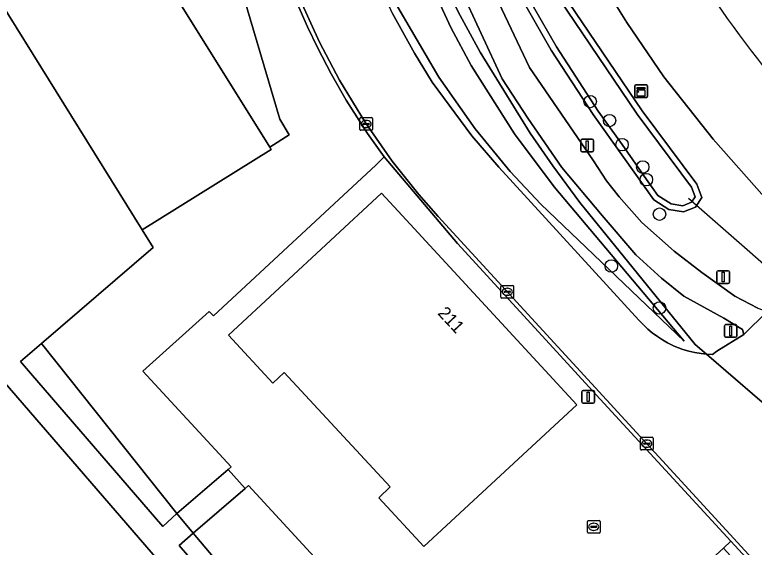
# Model space of a CAD drawing. Extents: x 156061 to 157804, y 383437 to 385640.
# Drawn here: x 157607.2 to 157665.5, y 383655.1 to 383697 of the extents above; entities that cross this region are included whole.
import ezdxf

# ---------------------------------------------------------------- set-up
doc = ezdxf.new("R2010")
doc.units = 0
for name, color, linetype in [('IMGEO_Berm_groen', 7, 'Continuous'), ('IMGEO_Boom', 7, 'Continuous'), ('IMGEO_Duiker', 7, 'Continuous'), ('IMGEO_Erf', 7, 'Continuous'), ('IMGEO_Fietspad_gesloten', 7, 'Continuous'), ('IMGEO_Grasland_overig', 7, 'Continuous'), ('IMGEO_Groenvoorziening', 7, 'Continuous'), ('IMGEO_Hek', 7, 'Continuous'), ('IMGEO_Kast', 7, 'Continuous'), ('IMGEO_Kolk', 7, 'Continuous'), ('IMGEO_Lichtmast', 7, 'Continuous'), ('IMGEO_Meer_plas_ven_vijver', 7, 'Continuous'), ('IMGEO_Oever', 7, 'Continuous'), ('IMGEO_Pand', 7, 'Continuous'), ('IMGEO_Pand_nummerreeks', 7, 'Continuous'), ('IMGEO_Rijbaan_lokaal_gesloten', 7, 'Continuous'), ('IMGEO_Rijbaan_lokaal_open', 7, 'Continuous'), ('IMGEO_Verkeersbordpaal', 7, 'Continuous'), ('IMGEO_Voetpad_gesloten', 7, 'Continuous'), ('IMGEO_Waterloop', 7, 'Continuous')]:
    doc.layers.add(name, color=color, linetype=linetype)

msp = doc.modelspace()

# ---------------------------------------------------------------- linework, layer by layer
at = {"layer": 'IMGEO_Berm_groen'}
msp.add_lwpolyline([(157656.632, 383689.474), (157660.937, 383683.676), (157661.345, 383682.627), (157660.835, 383681.881), (157659.893, 383681.496), (157658.745, 383681.699), (157657.555, 383682.443), (157652.785, 383689.179), (157649.474, 383694.263), (157647.042, 383698.509), (157644.296, 383704.009), (157630.634, 383737.612), (157621.052, 383760.833), (157597.456, 383819.12), (157599.565, 383819.919), (157622.01, 383766.684), (157628.75, 383750), (157632.796, 383738.492), (157645.394, 383707.875), (157649.283, 383700.352)], close=True, dxfattribs=at)
for points in [[(157619.12, 383759.995), (157619.272, 383759.605), (157619.425, 383759.216), (157621.18, 383754.837), (157623.144, 383750), (157627.643, 383739.156), (157638.747, 383712.974), (157643.168, 383702.614), (157647.755, 383692.88), (157652.793, 383685.539), (157653.818, 383683.942), (157654.817, 383682.694), (157656.624, 383680.676), (157659.165, 383678.4), (157661.336, 383676.722), (157663.95, 383674.865), (157665.764, 383673.914), (157666.48, 383673.644), (157666.827, 383674.423), (157667.128, 383675.025), (157667.375, 383675.651), (157667.541, 383676.205)], [(157666.28, 383682.654), (157662.238, 383687.235), (157658.348, 383692.157), (157655.418, 383696.421), (157653.189, 383700.032), (157646.921, 383712.29), (157641.684, 383723.88), (157630.958, 383750)]]:
    msp.add_lwpolyline(points, dxfattribs=at)
at = {"layer": 'IMGEO_Boom'}
for centre in [(157652.54, 383690.2), (157654.069, 383688.702), (157655.052, 383686.803), (157656.682, 383685.039), (157656.967, 383684.044), (157658.002, 383681.323), (157654.208, 383677.236), (157658.006, 383673.93)]:
    msp.add_circle(centre, 0.489, dxfattribs=at)
at = {"layer": 'IMGEO_Duiker'}
msp.add_lwpolyline([(157680.128, 383665.155), (157679.878, 383665.374), (157673.509, 383670.965), (157667.541, 383676.205), (157665.124, 383678.326), (157660.298, 383682.563)], dxfattribs=at)
at = {"layer": 'IMGEO_Erf'}
for points in [[(157634.437, 383638.653), (157620.132, 383655.218), (157621.256, 383656.181), (157619.968, 383657.726), (157618.847, 383656.716), (157608.419, 383668.784), (157607.636, 383669.704), (157609.282, 383671.12), (157618.102, 383678.709), (157617.211, 383680.099), (157604.846, 383699.969), (157614.994, 383706.315), (157627.287, 383686.608), (157628.823, 383687.576), (157628.075, 383688.812), (157620.719, 383713.705), (157622.915, 383714.315), (157620.859, 383719.471), (157613.417, 383738.127), (157582.968, 383711.822)], [(157546.586, 383690.669), (157569.551, 383710.587), (157574.434, 383704.864), (157580.09, 383698.235), (157589.181, 383706.103), (157593.316, 383701.326), (157584.203, 383693.494), (157589.969, 383686.975), (157592.085, 383684.583), (157592.743, 383683.81), (157631.604, 383638.864)]]:
    msp.add_lwpolyline(points, dxfattribs=at)
for points in [[(157663.038, 383655.013), (157663.63, 383655.554), (157652.735, 383667.414), (157649.055, 383671.421), (157642.073, 383679.016), (157636.298, 383685.833), (157635.64, 383685.18), (157622.846, 383673.301), (157622.498, 383673.653), (157617.28, 383668.944), (157624.23, 383661.417), (157624.003, 383661.197), (157625.333, 383659.711), (157625.613, 383659.933), (157645.162, 383638.719), (157646.075, 383639.53), (157646.224, 383639.429), (157647.765, 383640.669), (157647.565, 383640.888)], [(157639.423, 383655.14), (157635.882, 383658.959), (157636.783, 383659.847), (157628.424, 383668.849), (157627.528, 383668.013), (157624.022, 383671.797), (157636.09, 383682.98), (157637.392, 383681.569), (157651.485, 383666.295)]]:
    msp.add_lwpolyline(points, close=True, dxfattribs=at)
at = {"layer": 'IMGEO_Fietspad_gesloten'}
for points in [[(157620.857, 383750), (157625.641, 383738.364), (157636.444, 383712.133), (157640.636, 383702.745), (157645.615, 383692.003), (157647.612, 383688.893), (157650.31, 383684.991), (157653.473, 383681.227), (157656.137, 383678.12), (157658.153, 383676.273), (157659.933, 383674.868), (157663.084, 383673.125), (157664.534, 383672.23), (157664.66, 383671.828), (157666.48, 383673.644)], [(157665.764, 383673.914), (157663.95, 383674.865), (157661.336, 383676.722), (157659.165, 383678.4), (157656.624, 383680.676), (157654.817, 383682.694), (157653.818, 383683.942), (157652.793, 383685.539), (157647.755, 383692.88), (157643.168, 383702.614), (157638.747, 383712.974), (157627.643, 383739.156)]]:
    msp.add_lwpolyline(points, dxfattribs=at)
at = {"layer": 'IMGEO_Grasland_overig'}
for points in [[(157617.211, 383680.099), (157618.102, 383678.709), (157609.282, 383671.12), (157619.968, 383657.726), (157624.003, 383661.197), (157624.23, 383661.417), (157617.28, 383668.944), (157622.498, 383673.653), (157622.846, 383673.301), (157635.64, 383685.18), (157636.298, 383685.833), (157634.986, 383687.693), (157633.31, 383690.317), (157632.13, 383692.372), (157631.063, 383694.413), (157630.259, 383696.094), (157629.402, 383698.056), (157622.915, 383714.315), (157620.719, 383713.705), (157628.075, 383688.812), (157628.823, 383687.576), (157627.287, 383686.608), (157627.398, 383686.431)], [(157609.282, 383671.12), (157607.636, 383669.704), (157608.419, 383668.784), (157618.847, 383656.716), (157619.968, 383657.726)]]:
    msp.add_lwpolyline(points, close=True, dxfattribs=at)
at = {"layer": 'IMGEO_Groenvoorziening'}
for points in [[(157649.7, 383683.481), (157646.562, 383687.66), (157643.168, 383693.05), (157641.568, 383696.029), (157639.454, 383700.6), (157637.598, 383705.528), (157619.357, 383750), (157608.011, 383777.219), (157590.971, 383816.65), (157589.147, 383814.382), (157615.621, 383750), (157634.608, 383703.827), (157637.39, 383697.645), (157640.601, 383692.115), (157643.471, 383688.052), (157646.245, 383684.678), (157648.645, 383682.101), (157659.948, 383671.324)], [(157659.948, 383671.324), (157648.645, 383682.101), (157646.245, 383684.678), (157643.471, 383688.052), (157640.601, 383692.115), (157637.39, 383697.645), (157634.608, 383703.827), (157615.621, 383750), (157589.147, 383814.382), (157590.971, 383816.65), (157608.011, 383777.219), (157619.357, 383750), (157637.598, 383705.528), (157639.454, 383700.6), (157641.568, 383696.029), (157643.168, 383693.05), (157646.562, 383687.66), (157649.7, 383683.481)], [(157617.318, 383607.508), (157617.189, 383609.565), (157623.911, 383616.901), (157639.22, 383630.176), (157647.699, 383637.528), (157646.224, 383639.429), (157646.075, 383639.53), (157645.162, 383638.719), (157625.613, 383659.933), (157625.333, 383659.711), (157621.256, 383656.181), (157636.145, 383638.565), (157633.728, 383636.44), (157614.798, 383619.797), (157598.3, 383603.675), (157604.166, 383597.049), (157613.461, 383586.57), (157620.486, 383578.692), (157622.825, 383576.06), (157630.214, 383582.846), (157612.047, 383603.052)], [(157596.405, 383605.765), (157598.042, 383603.967), (157598.3, 383603.675), (157614.798, 383619.797), (157633.728, 383636.44), (157636.145, 383638.565), (157621.256, 383656.181), (157620.132, 383655.218), (157634.437, 383638.653), (157632.931, 383637.35)]]:
    msp.add_lwpolyline(points, close=True, dxfattribs=at)
for points in [[(157640.011, 383701.544), (157642.293, 383696.97), (157643.878, 383694.087), (157647.814, 383687.72), (157649.591, 383685.145), (157651.737, 383682.237), (157660.817, 383671.051), (157661.711, 383670.281), (157662.188, 383670.253), (157662.52, 383670.523), (157664.66, 383671.828), (157664.534, 383672.23), (157663.084, 383673.125), (157659.933, 383674.868), (157658.153, 383676.273), (157656.137, 383678.12), (157653.473, 383681.227), (157650.31, 383684.991), (157647.612, 383688.893), (157645.615, 383692.003), (157640.636, 383702.745)], [(157636.963, 383697.145), (157638.679, 383694.001), (157640.091, 383691.739), (157643.2, 383687.496), (157645.33, 383685.028), (157656.375, 383672.981), (157656.769, 383672.566), (157657.096, 383672.261), (157657.431, 383671.982), (157657.842, 383671.678), (157658.251, 383671.413), (157658.639, 383671.193), (157659.172, 383670.934), (157659.856, 383670.669), (157660.315, 383670.53), (157660.784, 383670.418), (157661.278, 383670.331), (157661.711, 383670.281), (157660.817, 383671.051), (157651.737, 383682.237), (157649.591, 383685.145), (157647.814, 383687.72), (157643.878, 383694.087), (157642.293, 383696.97), (157640.011, 383701.544)], [(157669.795, 383648.842), (157663.63, 383655.554), (157663.038, 383655.013), (157670.77, 383646.55)]]:
    msp.add_lwpolyline(points, dxfattribs=at)
msp.add_arc((157737.195, 383749.157), 90.556, 213.33611, 229.48121, dxfattribs=at)
at = {"layer": 'IMGEO_Hek'}
for points in [[(157661.711, 383670.281), (157660.817, 383671.051), (157651.737, 383682.237), (157649.591, 383685.145), (157647.814, 383687.72), (157643.878, 383694.087), (157642.293, 383696.97), (157640.011, 383701.544), (157637.106, 383708.345), (157620.09, 383750)], [(157667.614, 383665.197), (157661.711, 383670.281)]]:
    msp.add_lwpolyline(points, dxfattribs=at)
at = {"layer": 'IMGEO_Kast'}
for p, q in [((157656.052, 383690.585), (157656.052, 383691.426)), ((157656.052, 383691.426), (157656.052, 383690.585)), ((157656.127, 383691.51), (157656.968, 383691.51)), ((157656.968, 383691.51), (157656.127, 383691.51)), ((157657.052, 383691.435), (157657.052, 383690.594)), ((157657.052, 383690.594), (157657.052, 383691.435)), ((157656.977, 383690.51), (157656.136, 383690.51)), ((157656.136, 383690.51), (157656.977, 383690.51))]:
    msp.add_line(p, q, dxfattribs=at)
for points in [[(157656.247, 383691.3), (157656.847, 383691.3), (157656.847, 383691.215), (157656.247, 383691.215), (157656.247, 383691.3)], [(157656.247, 383691.125), (157656.847, 383691.125), (157656.847, 383690.636), (157656.247, 383690.636), (157656.247, 383691.125)]]:
    msp.add_lwpolyline(points, dxfattribs=at)
msp.add_circle((157656.331, 383690.974), 0.0377, dxfattribs=at)
for centre, start, end in [((157656.13, 383691.432), 92.4484, 184.28452), ((157656.13, 383691.432), 92.4484, 184.28452), ((157656.974, 383691.432), 2.4484, 94.28452), ((157656.974, 383691.432), 2.4484, 94.28452), ((157656.13, 383690.588), 182.4484, 274.28452), ((157656.13, 383690.588), 182.4484, 274.28452), ((157656.974, 383690.588), 272.4484, 4.28452), ((157656.974, 383690.588), 272.4484, 4.28452)]:
    msp.add_arc(centre, 0.0779, start, end, dxfattribs=at)
at = {"layer": 'IMGEO_Kolk'}
for p, q in [((157634.382, 383688.008), (157634.382, 383688.86)), ((157634.457, 383688.934), (157635.309, 383688.934)), ((157635.383, 383688.86), (157635.383, 383688.008)), ((157634.641, 383688.428), (157634.641, 383688.44)), ((157635.079, 383688.391), (157634.681, 383688.391)), ((157634.684, 383688.477), (157635.082, 383688.477)), ((157634.87, 383688.714), (157634.895, 383688.714)), ((157635.125, 383688.44), (157635.125, 383688.428)), ((157635.309, 383687.934), (157634.457, 383687.934)), ((157634.893, 383688.154), (157634.868, 383688.154)), ((157645.507, 383674.782), (157645.507, 383675.634)), ((157645.582, 383675.708), (157646.434, 383675.708)), ((157645.995, 383675.488), (157646.02, 383675.488)), ((157646.508, 383675.634), (157646.508, 383674.782)), ((157645.766, 383675.202), (157645.766, 383675.214)), ((157646.204, 383675.165), (157645.806, 383675.165)), ((157645.809, 383675.251), (157646.207, 383675.251)), ((157646.018, 383674.928), (157645.993, 383674.928)), ((157646.25, 383675.214), (157646.25, 383675.202)), ((157646.434, 383674.708), (157645.582, 383674.708)), ((157656.574, 383663.738), (157657.426, 383663.738)), ((157656.499, 383662.812), (157656.499, 383663.664)), ((157656.758, 383663.232), (157656.758, 383663.244)), ((157657.196, 383663.195), (157656.798, 383663.195)), ((157656.801, 383663.281), (157657.199, 383663.281)), ((157656.987, 383663.518), (157657.012, 383663.518)), ((157657.242, 383663.244), (157657.242, 383663.232)), ((157657.5, 383663.664), (157657.5, 383662.812)), ((157657.426, 383662.738), (157656.574, 383662.738)), ((157657.01, 383662.958), (157656.985, 383662.958)), ((157652.319, 383656.255), (157652.319, 383657.107)), ((157652.394, 383657.181), (157653.246, 383657.181)), ((157652.621, 383656.724), (157653.019, 383656.724)), ((157652.807, 383656.961), (157652.832, 383656.961)), ((157653.32, 383657.107), (157653.32, 383656.255)), ((157653.246, 383656.181), (157652.394, 383656.181)), ((157652.578, 383656.675), (157652.578, 383656.687)), ((157653.016, 383656.638), (157652.618, 383656.638)), ((157652.83, 383656.401), (157652.805, 383656.401)), ((157653.062, 383656.687), (157653.062, 383656.675))]:
    msp.add_line(p, q, dxfattribs=at)
for points in [[(157634.382, 383688.008), (157634.382, 383688.86)], [(157634.457, 383688.934), (157635.309, 383688.934)], [(157635.383, 383688.86), (157635.383, 383688.008)], [(157635.309, 383687.934), (157634.457, 383687.934)], [(157645.507, 383674.782), (157645.507, 383675.634)], [(157645.582, 383675.708), (157646.434, 383675.708)], [(157646.508, 383675.634), (157646.508, 383674.782)], [(157646.434, 383674.708), (157645.582, 383674.708)], [(157656.574, 383663.738), (157657.426, 383663.738)], [(157656.499, 383662.812), (157656.499, 383663.664)], [(157657.5, 383663.664), (157657.5, 383662.812)], [(157657.426, 383662.738), (157656.574, 383662.738)], [(157652.319, 383656.255), (157652.319, 383657.107)], [(157652.394, 383657.181), (157653.246, 383657.181)], [(157653.32, 383657.107), (157653.32, 383656.255)], [(157653.246, 383656.181), (157652.394, 383656.181)]]:
    msp.add_lwpolyline(points, dxfattribs=at)
for centre, radius, start, end in [((157634.459, 383688.858), 0.0765, 91.55205, 178.44795), ((157634.459, 383688.858), 0.0765, 91.55205, 178.44795), ((157635.307, 383688.858), 0.0765, 1.55205, 88.44795), ((157635.307, 383688.858), 0.0765, 1.55205, 88.44795), ((157634.681, 383688.437), 0.0403, 85.87752, 175.75265), ((157634.678, 383688.427), 0.0366, 178.93798, 274.71019), ((157635.082, 383688.434), 0.043, 264.86636, 352.45326), ((157635.086, 383688.439), 0.0386, 1.73085, 96.63898), ((157634.459, 383688.01), 0.0765, 181.55205, 268.44795), ((157634.459, 383688.01), 0.0765, 181.55205, 268.44795), ((157635.307, 383688.01), 0.0765, 271.55205, 358.44795), ((157635.307, 383688.01), 0.0765, 271.55205, 358.44795), ((157645.584, 383675.632), 0.0765, 91.55205, 178.44795), ((157645.584, 383675.632), 0.0765, 91.55205, 178.44795), ((157646.432, 383675.632), 0.0765, 1.55205, 88.44795), ((157646.432, 383675.632), 0.0765, 1.55205, 88.44795), ((157645.584, 383674.784), 0.0765, 181.55205, 268.44795), ((157645.584, 383674.784), 0.0765, 181.55205, 268.44795), ((157645.806, 383675.211), 0.0403, 85.87752, 175.75265), ((157645.803, 383675.201), 0.0366, 178.93798, 274.71019), ((157646.207, 383675.208), 0.043, 264.86636, 352.45326), ((157646.211, 383675.213), 0.0386, 1.73085, 96.63898), ((157646.432, 383674.784), 0.0765, 271.55205, 358.44795), ((157646.432, 383674.784), 0.0765, 271.55205, 358.44795), ((157656.576, 383663.662), 0.0765, 91.55205, 178.44795), ((157656.576, 383663.662), 0.0765, 91.55205, 178.44795), ((157657.424, 383663.662), 0.0765, 1.55205, 88.44795), ((157657.424, 383663.662), 0.0765, 1.55205, 88.44795), ((157656.798, 383663.241), 0.0403, 85.87752, 175.75265), ((157656.795, 383663.231), 0.0366, 178.93798, 274.71019), ((157657.199, 383663.238), 0.043, 264.86636, 352.45326), ((157657.203, 383663.243), 0.0386, 1.73085, 96.63898), ((157656.576, 383662.814), 0.0765, 181.55205, 268.44795), ((157656.576, 383662.814), 0.0765, 181.55205, 268.44795), ((157657.424, 383662.814), 0.0765, 271.55205, 358.44795), ((157657.424, 383662.814), 0.0765, 271.55205, 358.44795), ((157652.396, 383657.105), 0.0765, 91.55205, 178.44795), ((157652.396, 383657.105), 0.0765, 91.55205, 178.44795), ((157652.618, 383656.684), 0.0403, 85.87752, 175.75265), ((157653.023, 383656.686), 0.0386, 1.73085, 96.63898), ((157653.244, 383657.105), 0.0765, 1.55205, 88.44795), ((157653.244, 383657.105), 0.0765, 1.55205, 88.44795), ((157652.396, 383656.257), 0.0765, 181.55205, 268.44795), ((157652.396, 383656.257), 0.0765, 181.55205, 268.44795), ((157652.615, 383656.674), 0.0366, 178.93798, 274.71019), ((157653.019, 383656.681), 0.043, 264.86636, 352.45326), ((157653.244, 383656.257), 0.0765, 271.55205, 358.44795), ((157653.244, 383656.257), 0.0765, 271.55205, 358.44795)]:
    msp.add_arc(centre, radius, start, end, dxfattribs=at)
for centre, major_axis, ratio, start_param, end_param in [((157634.869, 383688.434), (-0.387, 0.002), 0.722429, 4.712389, 7.853982), ((157634.894, 383688.434), (-0.39, 0.002), 0.717154, 1.570796, 4.712389), ((157645.994, 383675.208), (-0.387, 0.002), 0.722429, 4.712389, 7.853982), ((157646.019, 383675.208), (-0.39, 0.002), 0.717154, 1.570796, 4.712389), ((157656.986, 383663.238), (-0.387, 0.002), 0.722429, 4.712389, 7.853982), ((157657.011, 383663.238), (-0.39, 0.002), 0.717154, 1.570796, 4.712389), ((157652.806, 383656.681), (-0.387, 0.002), 0.722429, 4.712389, 7.853982), ((157652.831, 383656.681), (-0.39, 0.002), 0.717154, 1.570796, 4.712389)]:
    msp.add_ellipse(centre, major_axis=major_axis, ratio=ratio, start_param=start_param, end_param=end_param, dxfattribs=at)
at = {"layer": 'IMGEO_Lichtmast'}
for p, q in [((157651.802, 383686.33), (157651.802, 383687.13)), ((157651.802, 383687.13), (157651.802, 383686.33)), ((157651.902, 383687.23), (157652.692, 383687.23)), ((157652.692, 383687.23), (157651.902, 383687.23)), ((157652.792, 383687.13), (157652.792, 383686.33)), ((157652.792, 383686.33), (157652.792, 383687.13)), ((157652.692, 383686.23), (157651.902, 383686.23)), ((157651.902, 383686.23), (157652.692, 383686.23)), ((157651.883, 383666.528), (157651.883, 383667.328)), ((157651.883, 383667.328), (157651.883, 383666.528)), ((157651.983, 383667.428), (157652.773, 383667.428)), ((157652.773, 383667.428), (157651.983, 383667.428)), ((157652.873, 383667.328), (157652.873, 383666.528)), ((157652.873, 383666.528), (157652.873, 383667.328)), ((157652.773, 383666.428), (157651.983, 383666.428)), ((157651.983, 383666.428), (157652.773, 383666.428))]:
    msp.add_line(p, q, dxfattribs=at)
for points in [[(157652.222, 383687.105), (157652.372, 383687.105), (157652.372, 383686.355), (157652.222, 383686.355), (157652.222, 383687.105)], [(157652.303, 383667.303), (157652.453, 383667.303), (157652.453, 383666.553), (157652.303, 383666.553), (157652.303, 383667.303)]]:
    msp.add_lwpolyline(points, dxfattribs=at)
for centre, start, end in [((157651.902, 383687.13), 90, 180), ((157651.902, 383687.13), 90, 180), ((157652.692, 383687.13), 0, 90), ((157652.692, 383687.13), 360, 90), ((157651.902, 383686.33), 180, 270), ((157651.902, 383686.33), 180, 270), ((157652.692, 383686.33), 270, 0), ((157652.692, 383686.33), 270, 0), ((157651.983, 383667.328), 90, 180), ((157651.983, 383667.328), 90, 180), ((157652.773, 383667.328), 0, 90), ((157652.773, 383667.328), 360, 90), ((157651.983, 383666.528), 180, 270), ((157651.983, 383666.528), 180, 270), ((157652.773, 383666.528), 270, 0), ((157652.773, 383666.528), 270, 0)]:
    msp.add_arc(centre, 0.1, start, end, dxfattribs=at)
at = {"layer": 'IMGEO_Meer_plas_ven_vijver'}
msp.add_lwpolyline([(157536.954, 383682.315), (157537.085, 383682.162), (157532.924, 383678.599), (157532.815, 383678.725), (157532.494, 383678.447), (157553.514, 383655.202), (157554.504, 383654.072), (157594.504, 383606.759), (157594.683, 383606.913), (157595.061, 383607.241), (157603.332, 383614.398), (157604.478, 383615.391), (157631.604, 383638.864), (157592.743, 383683.81), (157592.085, 383684.583), (157589.969, 383686.975), (157584.203, 383693.494), (157593.316, 383701.326), (157589.181, 383706.103), (157580.09, 383698.235), (157574.434, 383704.864), (157569.551, 383710.587), (157546.586, 383690.669), (157545.842, 383690.024)], close=True, dxfattribs=at)
at = {"layer": 'IMGEO_Oever'}
msp.add_lwpolyline([(157632.796, 383738.492), (157628.75, 383750), (157622.01, 383766.684), (157599.565, 383819.919), (157597.456, 383819.12), (157621.052, 383760.833), (157630.634, 383737.612), (157644.296, 383704.009), (157647.042, 383698.509), (157649.474, 383694.263), (157652.785, 383689.179), (157657.555, 383682.443), (157658.745, 383681.699), (157659.893, 383681.496), (157660.835, 383681.881), (157661.345, 383682.627), (157660.937, 383683.676), (157656.632, 383689.474), (157649.283, 383700.352), (157645.394, 383707.875)], close=True, dxfattribs=at)
msp.add_lwpolyline([(157628.311, 383749.834), (157632.358, 383738.325), (157644.968, 383707.678), (157648.879, 383700.112), (157656.249, 383689.203), (157660.523, 383683.447), (157660.818, 383682.687), (157660.527, 383682.262), (157659.841, 383681.981), (157658.916, 383682.145), (157657.883, 383682.791), (157656.967, 383684.044), (157655.052, 383686.803), (157653.173, 383689.443), (157649.874, 383694.508), (157647.456, 383698.73), (157644.724, 383704.202), (157631.068, 383737.79), (157628.743, 383743.459)], dxfattribs=at)
at = {"layer": 'IMGEO_Pand'}
for points in [[(157627.287, 383686.608), (157614.994, 383706.315), (157604.846, 383699.969), (157617.211, 383680.099), (157627.398, 383686.431)], [(157637.392, 383681.569), (157636.09, 383682.98), (157624.022, 383671.797), (157627.528, 383668.013), (157628.424, 383668.849), (157636.783, 383659.847), (157635.882, 383658.959), (157639.423, 383655.14), (157651.485, 383666.295)]]:
    msp.add_lwpolyline(points, close=True, dxfattribs=at)
at = {"layer": 'IMGEO_Rijbaan_lokaal_gesloten'}
for points in [[(157595.701, 383836.038), (157602.956, 383818.231), (157609.325, 383802.679), (157625.684, 383762.843), (157630.958, 383750), (157641.684, 383723.88), (157646.921, 383712.29), (157653.189, 383700.032), (157655.418, 383696.421), (157658.348, 383692.157), (157662.238, 383687.235), (157666.28, 383682.654), (157677.949, 383671.748), (157678.956, 383671.117)], [(157609.012, 383750), (157629.704, 383698.154), (157631.195, 383694.874), (157632.775, 383691.884), (157634.822, 383688.528), (157636.942, 383685.511), (157639.039, 383682.875), (157640.558, 383681.144), (157670.038, 383649.042)], [(157667.614, 383665.197), (157661.711, 383670.281), (157661.278, 383670.331), (157660.784, 383670.418), (157660.315, 383670.53), (157659.856, 383670.669), (157659.172, 383670.934), (157658.639, 383671.193), (157658.251, 383671.413), (157657.842, 383671.678), (157657.431, 383671.982), (157657.096, 383672.261), (157656.769, 383672.566), (157656.375, 383672.981), (157645.33, 383685.028), (157643.2, 383687.496), (157640.091, 383691.739), (157638.679, 383694.001), (157636.963, 383697.145), (157635.183, 383701.072), (157614.923, 383750)], [(157667.541, 383676.205), (157667.375, 383675.651), (157667.128, 383675.025), (157666.827, 383674.423), (157666.48, 383673.644), (157664.66, 383671.828), (157662.52, 383670.523), (157662.188, 383670.253), (157661.711, 383670.281), (157667.614, 383665.197), (157668.052, 383665.774), (157669.038, 383667.332), (157671.072, 383670.09), (157671.728, 383670.394), (157672.606, 383670.719), (157673.509, 383670.965)]]:
    msp.add_lwpolyline(points, dxfattribs=at)
msp.add_arc((157737.195, 383749.157), 90.556, 213.33611, 229.48121, dxfattribs=at)
at = {"layer": 'IMGEO_Rijbaan_lokaal_open'}
for points in [[(157608.681, 383750), (157613.417, 383738.127), (157620.859, 383719.471), (157622.915, 383714.315), (157629.402, 383698.056), (157630.259, 383696.094), (157631.063, 383694.413), (157632.13, 383692.372), (157633.31, 383690.317), (157634.986, 383687.693), (157636.298, 383685.833), (157642.073, 383679.016), (157649.055, 383671.421), (157652.735, 383667.414), (157663.63, 383655.554), (157669.795, 383648.842)], [(157670.038, 383649.042), (157640.558, 383681.144), (157639.039, 383682.875), (157636.942, 383685.511), (157634.822, 383688.528), (157632.775, 383691.884), (157631.195, 383694.874), (157629.704, 383698.154), (157609.012, 383750)]]:
    msp.add_lwpolyline(points, dxfattribs=at)
at = {"layer": 'IMGEO_Verkeersbordpaal'}
for p, q in [((157662.528, 383675.968), (157662.528, 383676.768)), ((157662.528, 383676.768), (157662.528, 383675.968)), ((157662.628, 383676.868), (157663.418, 383676.868)), ((157663.418, 383676.868), (157662.628, 383676.868)), ((157663.518, 383676.768), (157663.518, 383675.968)), ((157663.518, 383675.968), (157663.518, 383676.768)), ((157663.418, 383675.868), (157662.628, 383675.868)), ((157662.628, 383675.868), (157663.418, 383675.868)), ((157663.117, 383671.718), (157663.117, 383672.518)), ((157663.117, 383672.518), (157663.117, 383671.718)), ((157663.217, 383672.618), (157664.007, 383672.618)), ((157664.007, 383672.618), (157663.217, 383672.618)), ((157664.107, 383672.518), (157664.107, 383671.718)), ((157664.107, 383671.718), (157664.107, 383672.518)), ((157664.007, 383671.618), (157663.217, 383671.618)), ((157663.217, 383671.618), (157664.007, 383671.618))]:
    msp.add_line(p, q, dxfattribs=at)
for points in [[(157662.948, 383676.743), (157663.098, 383676.743), (157663.098, 383675.993), (157662.948, 383675.993), (157662.948, 383676.743)], [(157663.537, 383672.493), (157663.687, 383672.493), (157663.687, 383671.743), (157663.537, 383671.743), (157663.537, 383672.493)]]:
    msp.add_lwpolyline(points, dxfattribs=at)
for centre, start, end in [((157662.628, 383676.768), 90, 180), ((157662.628, 383676.768), 90, 180), ((157663.418, 383676.768), 0, 90), ((157663.418, 383676.768), 360, 90), ((157662.628, 383675.968), 180, 270), ((157662.628, 383675.968), 180, 270), ((157663.418, 383675.968), 270, 0), ((157663.418, 383675.968), 270, 0), ((157663.217, 383672.518), 90, 180), ((157663.217, 383672.518), 90, 180), ((157664.007, 383672.518), 0, 90), ((157664.007, 383672.518), 360, 90), ((157663.217, 383671.718), 180, 270), ((157663.217, 383671.718), 180, 270), ((157664.007, 383671.718), 270, 0), ((157664.007, 383671.718), 270, 0)]:
    msp.add_arc(centre, 0.1, start, end, dxfattribs=at)
at = {"layer": 'IMGEO_Voetpad_gesloten'}
msp.add_lwpolyline([(157619.968, 383657.726), (157621.256, 383656.181), (157625.333, 383659.711), (157624.003, 383661.197)], close=True, dxfattribs=at)
at = {"layer": 'IMGEO_Waterloop'}
msp.add_lwpolyline([(157628.743, 383743.459), (157631.068, 383737.79), (157644.724, 383704.202), (157647.456, 383698.73), (157649.874, 383694.508), (157653.173, 383689.443), (157655.052, 383686.803), (157656.967, 383684.044), (157657.883, 383682.791), (157658.916, 383682.145), (157659.841, 383681.981), (157660.527, 383682.262), (157660.818, 383682.687), (157660.523, 383683.447), (157656.249, 383689.203), (157648.879, 383700.112), (157644.968, 383707.678), (157632.358, 383738.325), (157628.311, 383749.834)], dxfattribs=at)

# ---------------------------------------------------------------- texts
at = {"layer": 'IMGEO_Pand_nummerreeks'}
msp.add_text('211', height=1, rotation=312.88759, dxfattribs=at).set_placement((157640.464, 383673.477))

doc.saveas('drawing.dxf')
